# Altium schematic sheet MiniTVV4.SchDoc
size A; SheetNumber: 1; SheetTotal: 1
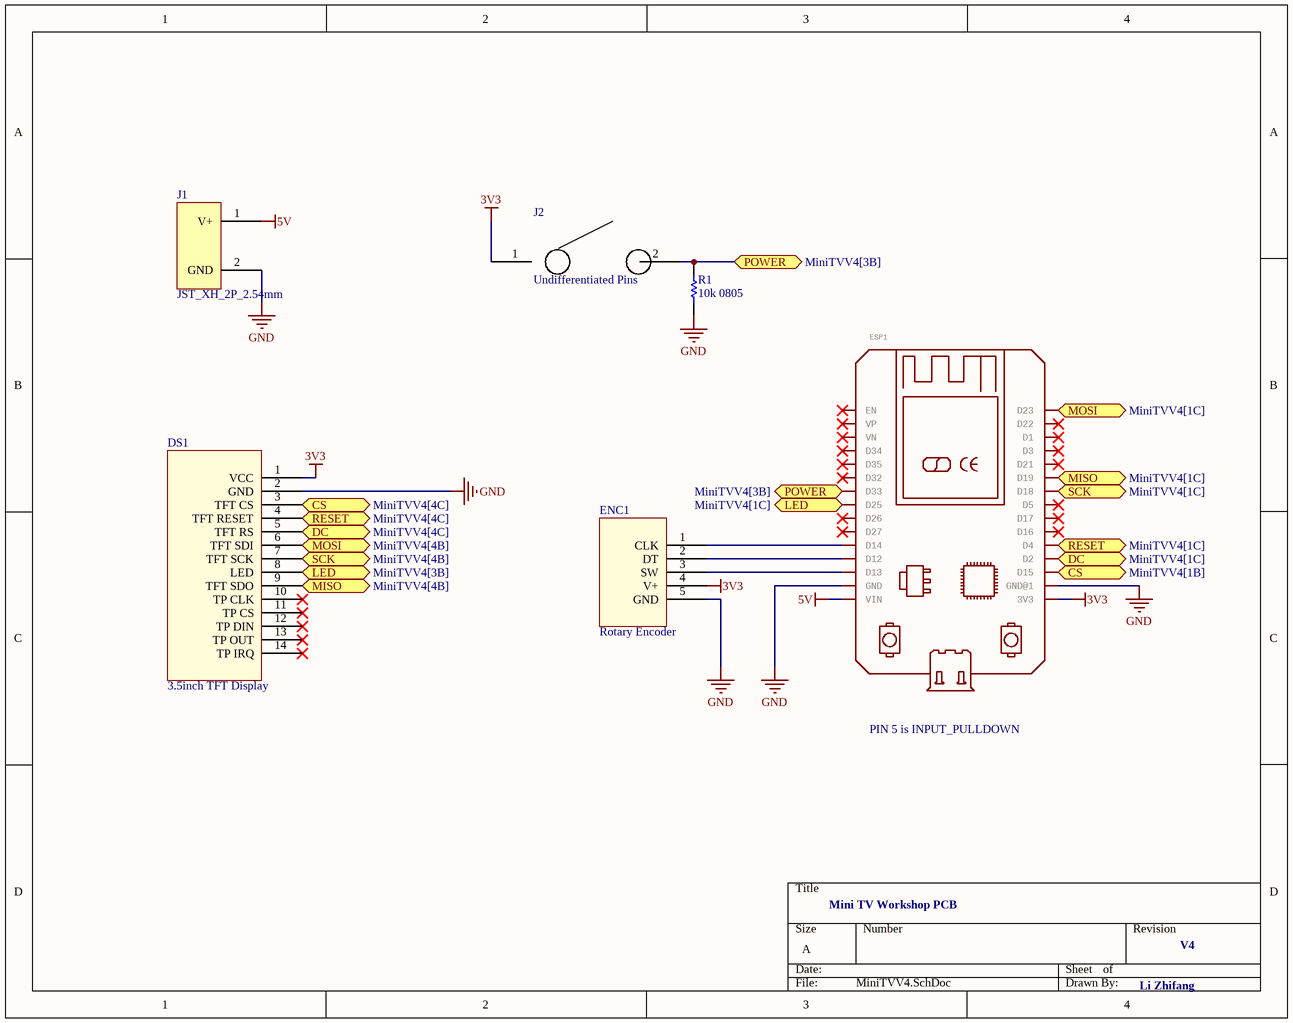
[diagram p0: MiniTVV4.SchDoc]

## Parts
DS1  3.5inch TFT Display  [3.5inch SPI Display]
ENC1  Rotary Encoder  [Rotary Encoder]
ESP1  https://github.com/shridattdudhat  [ESP32-DEVKITV1]  (value not drawn)
J1  JST_XH_2P_2.54mm  [JST_XH_2P_2.54mm]
J2  Undifferentiated Pins  [2-Pin 2.54mm]
R1  10k 0805  [RESC2013X60X35NL10T20]

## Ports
CS (bidir, see MiniTVV4[1B]), CS (bidir, see MiniTVV4[4C]), DC (bidir, see MiniTVV4[1C]), DC (bidir, see MiniTVV4[4C]), LED (bidir, see MiniTVV4[1C]), LED (bidir, see MiniTVV4[3B]), MISO (bidir, see MiniTVV4[1C]), MISO (bidir, see MiniTVV4[4B]), MOSI (bidir, see MiniTVV4[1C]), MOSI (bidir, see MiniTVV4[4B]), POWER (bidir, see MiniTVV4[3B]), RESET (bidir, see MiniTVV4[1C]), RESET (bidir, see MiniTVV4[4C]), SCK (bidir, see MiniTVV4[1C]), SCK (bidir, see MiniTVV4[4B])

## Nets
3V3: DS1.1(VCC) ENC1.4(V+) ESP1.3V3 J2.1
5V: ESP1.VIN J1.1(V+)
GND: DS1.2(GND) ENC1.5(GND) ESP1.GND ESP1.GND@1 J1.2(GND) R1.1
CS: DS1.3(TFT_CS) ESP1.D15 ; port CS
DC: DS1.5(TFT_RS) ESP1.D2 ; port DC
LED: DS1.8(LED) ESP1.D25 ; port LED
MISO: DS1.9(TFT_SDO) ESP1.D19 ; port MISO
MOSI: DS1.6(TFT_SDI) ESP1.D23 ; port MOSI
POWER: ESP1.D33 J2.2 R1.2 ; port POWER
RESET: DS1.4(TFT_RESET) ESP1.D4 ; port RESET
SCK: DS1.7(TFT_SCK) ESP1.D18 ; port SCK
NetENC1_1: ENC1.1(CLK) ESP1.D14
NetENC1_2: ENC1.2(DT) ESP1.D12
NetENC1_3: ENC1.3(SW) ESP1.D13

Not connected (* = marked no-connect by the designer): DS1 10(TP_CLK)* 11(TP_CS)* 12(TP_DIN)* 13(TP_OUT)* 14(TP_IRQ)*; ESP1 D1* D3* D5* D16* D17* D21* D22* D26* D27* D32* D34* D35* EN* VN* VP*

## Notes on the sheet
- PIN 5 is INPUT_PULLDOWN
- Mini TV Workshop PCB
- Li Zhifang
- V4

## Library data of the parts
ESP1 = ESP32DEVKITV1: GateName_1: G$1
J2 = SPST 2-Pin
R1 = CMP-2001-04523-1: Part Number: RC0805FR-104K7L; Manufacturer: Yageo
